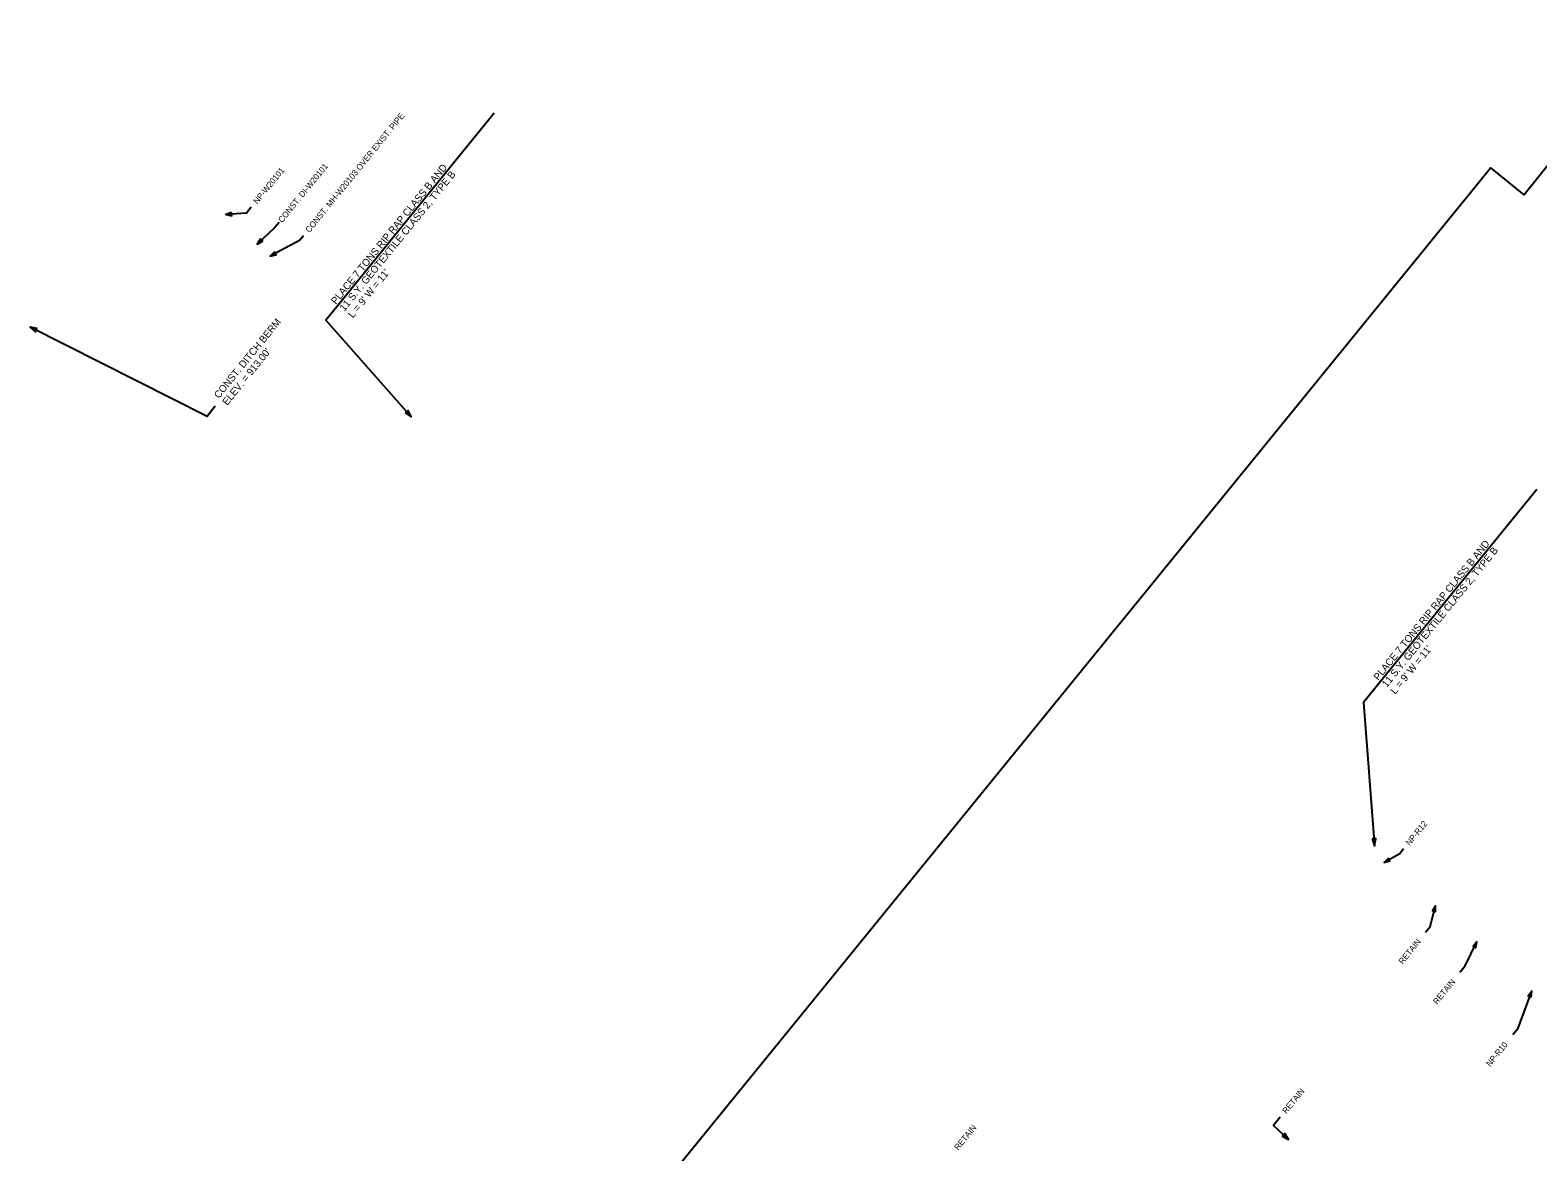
# Model space of a CAD drawing. Extents: x 1615497 to 1617608, y 1099429 to 1101318.
# Drawn here: x 1615497 to 1616750, y 1100352 to 1101285 of the extents above; entities that cross this region are included whole.
import ezdxf

# ---------------------------------------------------------------- set-up
doc = ezdxf.new("R2010")
doc.units = 0
doc.layers.add('RD_EX_Misc', color=7, linetype='Continuous')
doc.layers.add('RD_HC_Data_Rel', color=7, linetype='Continuous')

msp = doc.modelspace()

# ---------------------------------------------------------------- linework, layer by layer
at = {"layer": 'RD_EX_Misc'}
msp.add_lwpolyline([(1616368.7, 1099765.8), (1616621.6, 1099560), (1617489.2, 1100625.8), (1617256.2, 1100856.1), (1617080.1, 1101099), (1616848.9, 1101284.7), (1616739.1, 1101147.9), (1616711.3, 1101170.2), (1615865, 1100129.8), (1615884.6, 1100113.8), (1615821.9, 1100036.8), (1616095.1, 1099888.9)], close=True, dxfattribs=at)
msp.add_lwpolyline([(1616368.7, 1099765.8), (1616621.6, 1099560), (1617489.2, 1100625.8), (1617256.2, 1100856.1), (1617080.1, 1101099), (1616848.9, 1101284.7), (1616739.1, 1101147.9), (1616711.3, 1101170.2), (1615865, 1100129.8), (1615884.6, 1100113.8), (1615821.9, 1100036.8), (1616095.1, 1099888.9)], close=True, dxfattribs=at)
msp.add_lwpolyline([(1616368.7, 1099765.8), (1616621.6, 1099560), (1617489.2, 1100625.8), (1617256.2, 1100856.1), (1617080.1, 1101099), (1616848.9, 1101284.7), (1616739.1, 1101147.9), (1616711.3, 1101170.2), (1615865, 1100129.8), (1615884.6, 1100113.8), (1615821.9, 1100036.8), (1616095.1, 1099888.9)], close=True, dxfattribs=at)
msp.add_lwpolyline([(1616368.7, 1099765.8), (1616621.6, 1099560), (1617489.2, 1100625.8), (1617256.2, 1100856.1), (1617080.1, 1101099), (1616848.9, 1101284.7), (1616739.1, 1101147.9), (1616711.3, 1101170.2), (1615865, 1100129.8), (1615884.6, 1100113.8), (1615821.9, 1100036.8), (1616095.1, 1099888.9)], close=True, dxfattribs=at)
msp.add_lwpolyline([(1616368.7, 1099765.8), (1616621.6, 1099560), (1617489.2, 1100625.8), (1617256.2, 1100856.1), (1617080.1, 1101099), (1616848.9, 1101284.7), (1616739.1, 1101147.9), (1616711.3, 1101170.2), (1615865, 1100129.8), (1615884.6, 1100113.8), (1615821.9, 1100036.8), (1616095.1, 1099888.9)], close=True, dxfattribs=at)
at = {"layer": 'RD_HC_Data_Rel'}
for p, q in [((1615883.1, 1101215.6), (1615748.6, 1101050.3)), ((1616749.5, 1100902.8), (1616614.9, 1100737.5))]:
    msp.add_line(p, q, dxfattribs=at)
for points in [[(1615681, 1101137.4), (1615677, 1101132.4), (1615659.9, 1101131.4)], [(1615704.3, 1101124.9), (1615700.5, 1101120.3), (1615686.1, 1101106.8)], [(1615724.4, 1101113.6), (1615721.3, 1101109.8), (1615696.8, 1101096.9)], [(1615748.6, 1101050.3), (1615743.1, 1101043.5), (1615814, 1100963.2)], [(1615651.2, 1100972), (1615644.4, 1100963.6), (1615497.3, 1101037.8)], [(1616614.9, 1100737.5), (1616605.4, 1100725.8), (1616614.7, 1100606.7)], [(1616638.8, 1100604), (1616635.6, 1100600), (1616622.6, 1100592.8)], [(1616657, 1100534.9), (1616660.8, 1100539.5), (1616665.3, 1100556.7)], [(1616685.6, 1100501.5), (1616689.9, 1100506.8), (1616699.8, 1100526.7)], [(1616729.7, 1100449.8), (1616733.9, 1100454.9), (1616745.3, 1100485.7)], [(1616536.3, 1100381.1), (1616530.6, 1100374.1), (1616543.2, 1100362.5)]]:
    msp.add_lwpolyline(points, dxfattribs=at)
for points in [[(1615664.6, 1101133), (1615659.9, 1101131.4), (1615664.8, 1101130.4)], [(1615688.7, 1101111.1), (1615686.1, 1101106.8), (1615690.5, 1101109.2)], [(1615700.5, 1101100.3), (1615696.8, 1101096.9), (1615701.7, 1101098)], [(1615503.2, 1101036.6), (1615497.3, 1101037.8), (1615501.8, 1101033.8)], [(1615809, 1100966.5), (1615814, 1100963.2), (1615811.4, 1100968.5)], [(1616612.7, 1100612.3), (1616614.7, 1100606.7), (1616615.8, 1100612.6)], [(1616626.2, 1100596.3), (1616622.6, 1100592.8), (1616627.5, 1100594)], [(1616665.3, 1100551.7), (1616665.3, 1100556.7), (1616662.8, 1100552.4)], [(1616698.8, 1100521.8), (1616699.8, 1100526.7), (1616696.5, 1100522.9)], [(1616744.8, 1100480.7), (1616745.3, 1100485.7), (1616742.4, 1100481.6)], [(1616537.9, 1100365.3), (1616543.2, 1100362.5), (1616540, 1100367.5)]]:
    msp.add_lwpolyline(points, close=True, dxfattribs=at)

# ---------------------------------------------------------------- texts
for s, height, p in [('CONST. MH-W20103 OVER EXIST. PIPE', 5, (1615729.5, 1101115.9)), ('NP-W20101', 5, (1615686.1, 1101139.7)), ('CONST. DI-W20101', 5, (1615706.8, 1101124.1)), ('PLACE 7 TONS RIP RAP CLASS B AND', 6, (1615751.5, 1101056.2)), ('11 S.Y. GEOTEXTILE CLASS 2, TYPE B', 6, (1615758.5, 1101050.5)), ("L = 9' W = 11'", 6, (1615765.5, 1101044.9)), ('CONST. DITCH BERM', 6, (1615654.2, 1100978)), ("ELEV. = 913.00'", 6, (1615661.1, 1100972.3)), ('PLACE 7 TONS RIP RAP CLASS B AND', 6, (1616617.9, 1100743.5)), ('11 S.Y. GEOTEXTILE CLASS 2, TYPE B', 6, (1616624.8, 1100737.8)), ("L = 9' W = 11'", 6, (1616631.8, 1100732.1)), ('NP-R12', 5, (1616643.9, 1100606.3)), ('RETAIN', 5, (1616638.1, 1100507.7)), ('RETAIN', 5, (1616666.7, 1100474.3)), ('NP-R10', 5, (1616710.7, 1100422.6)), ('RETAIN', 5, (1616541.4, 1100383.4)), ('RETAIN', 5, (1616268.7, 1100353.1))]:
    msp.add_text(s, height=height, rotation=50.8545, dxfattribs=at).set_placement(p)

doc.saveas('drawing.dxf')
